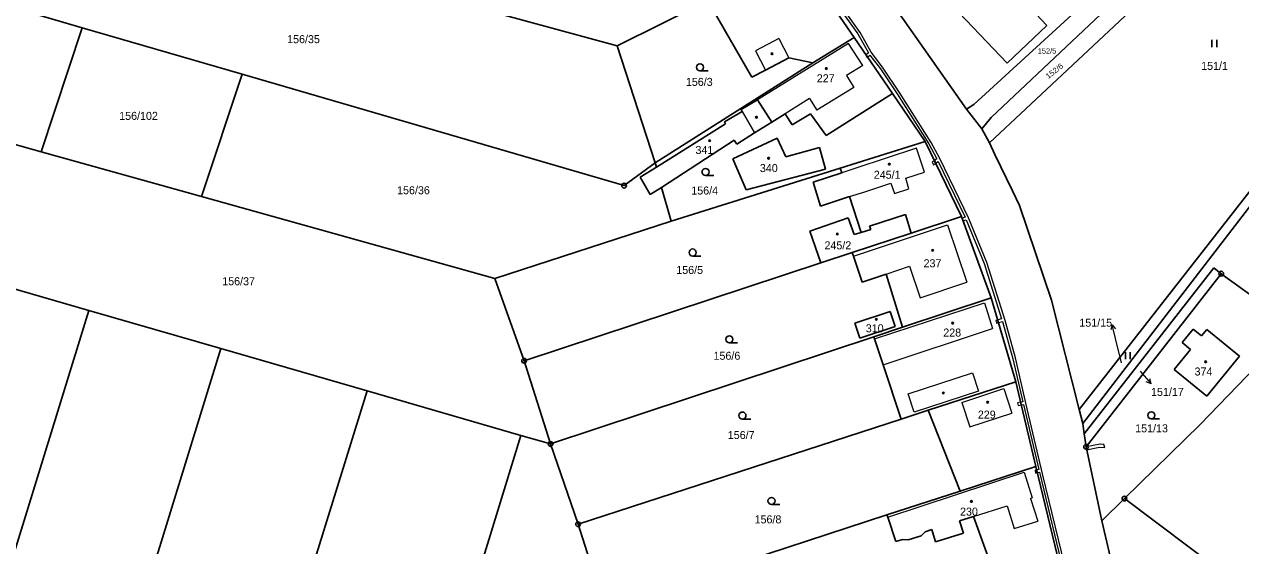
# Model space of a CAD drawing. Extents: x -694609 to -690140, y -1033292 to -1029794.
# Drawn here: x -693215.9 to -692957.6, y -1031527.4 to -1031416.8 of the extents above; entities that cross this region are included whole.
import ezdxf
from ezdxf.enums import TextEntityAlignment as Align

# ---------------------------------------------------------------- set-up
doc = ezdxf.new("R2010")
doc.units = 0
doc.header["$LTSCALE"] = 0.68
for name, color, linetype, lineweight in [('1', 7, 'Continuous', 25), ('13', 7, 'Continuous', 13), ('3', 7, 'Continuous', 25), ('4', 7, 'Continuous', 13), ('5', 7, 'Continuous', 25), ('7', 7, 'Continuous', 13), ('8', 7, 'Continuous', 25)]:
    doc.layers.add(name, color=color, linetype=linetype, lineweight=lineweight)
doc.layers.add('2', color=7, linetype='Continuous')

msp = doc.modelspace()

# ---------------------------------------------------------------- linework, layer by layer
at = {"layer": '1'}
for p, q in [((-693051.61, -1031402.21), (-693039.68, -1031419.57)), ((-693011.83, -1031403.18), (-692998.78, -1031416.98)), ((-693237.08, -1031407.73), (-693203.62, -1031417.48)), ((-693140.45, -1031407.6), (-693090.02, -1031421.29)), ((-693014.28, -1031433.8), (-692986.21, -1031408.04)), ((-693070.81, -1031411.75), (-693090.02, -1031421.29)), ((-693070.81, -1031411.75), (-693061.47, -1031427.99)), ((-693015.83, -1031434.75), (-693033.09, -1031410.25)), ((-693020.29, -1031411.17), (-693007.24, -1031424.98)), ((-692983.67, -1031411.06), (-693010.61, -1031436.53)), ((-692981.2, -1031414), (-693010.99, -1031441.88)), ((-693007.24, -1031424.98), (-692998.78, -1031416.98)), ((-693212.35, -1031443.81), (-693203.62, -1031417.48)), ((-693203.62, -1031417.48), (-693169.7, -1031427.36)), ((-693048.52, -1031424.96), (-693039.68, -1031419.57)), ((-693039.68, -1031419.57), (-693031.59, -1031431.43)), ((-693090.02, -1031421.29), (-693081.98, -1031446.14)), ((-693048.52, -1031424.96), (-693081.98, -1031446.14)), ((-693058.55, -1031426.46), (-693053.6, -1031423.87)), ((-693053.6, -1031423.87), (-693048.52, -1031424.96)), ((-693178.3, -1031453.32), (-693169.7, -1031427.36)), ((-693169.7, -1031427.36), (-693088.55, -1031451)), ((-693061.47, -1031427.99), (-693058.55, -1031426.46)), ((-693031.59, -1031431.43), (-693045.62, -1031440.32)), ((-693031.59, -1031431.43), (-693024.65, -1031441.66)), ((-693063.49, -1031435.23), (-693067.26, -1031437.47)), ((-693060.21, -1031432.75), (-693063.69, -1031434.87)), ((-693063.69, -1031434.87), (-693063.49, -1031435.23)), ((-693060.21, -1031432.75), (-693057.2, -1031437.53)), ((-693015.83, -1031434.75), (-693014.28, -1031433.8)), ((-693012.6, -1031438.91), (-693015.83, -1031434.75)), ((-692991.15, -1031501.5), (-692938.66, -1031433.21)), ((-693067.04, -1031437.88), (-693081.68, -1031447.05)), ((-693067.04, -1031437.88), (-693067.26, -1031437.47)), ((-693057.2, -1031437.53), (-693060.84, -1031439.82)), ((-693054.39, -1031435.77), (-693057.2, -1031437.53)), ((-693052.85, -1031438.09), (-693054.39, -1031435.77)), ((-693052.85, -1031438.09), (-693048.98, -1031435.74)), ((-693045.62, -1031440.32), (-693048.98, -1031435.74)), ((-693012.6, -1031438.91), (-693010.61, -1031436.53)), ((-693060.84, -1031439.82), (-693064.61, -1031442.21)), ((-693010.99, -1031441.88), (-693012.6, -1031438.91)), ((-693080.65, -1031451.39), (-693065.18, -1031441.34)), ((-693056.05, -1031440.94), (-693065.46, -1031445.3)), ((-693064.61, -1031442.21), (-693065.18, -1031441.34)), ((-693056.05, -1031440.94), (-693054.22, -1031444.86)), ((-693054.22, -1031444.86), (-693047.05, -1031442.92)), ((-693045.81, -1031447.51), (-693047.05, -1031442.92)), ((-693024.65, -1031441.66), (-693042.68, -1031447.28)), ((-693016.92, -1031457.57), (-693024.65, -1031441.66)), ((-693010.99, -1031441.88), (-693009.87, -1031444.42)), ((-693212.35, -1031443.81), (-693178.3, -1031453.32)), ((-693065.46, -1031445.3), (-693062.66, -1031451.92)), ((-693009.87, -1031444.42), (-693006.07, -1031452.07)), ((-693081.98, -1031446.14), (-693088.55, -1031451)), ((-693081.68, -1031447.05), (-693085.14, -1031449.22)), ((-693081.98, -1031446.14), (-693081.68, -1031447.05)), ((-693042.68, -1031447.28), (-693078.54, -1031458.51)), ((-693062.66, -1031451.92), (-693045.81, -1031447.51)), ((-693042.35, -1031448.28), (-693042.68, -1031447.28)), ((-692991.91, -1031498.52), (-692952.37, -1031447.9)), ((-693085.14, -1031449.22), (-693083.05, -1031452.89)), ((-693048.41, -1031450.23), (-693042.35, -1031448.28)), ((-693046.85, -1031455.33), (-693048.41, -1031450.23)), ((-693178.3, -1031453.32), (-693116, -1031470.7)), ((-693083.05, -1031452.89), (-693080.65, -1031451.39)), ((-693080.65, -1031451.39), (-693078.54, -1031458.51)), ((-693040.69, -1031453.33), (-693046.85, -1031455.33)), ((-693038.2, -1031460.91), (-693040.69, -1031453.33)), ((-693006.07, -1031452.07), (-693004.58, -1031455.21)), ((-693004.58, -1031455.21), (-692997.84, -1031475.31)), ((-693078.54, -1031458.51), (-693116, -1031470.7)), ((-693041, -1031457.81), (-693049.14, -1031460.66)), ((-693039.73, -1031461.39), (-693041, -1031457.81)), ((-693028.84, -1031457.1), (-693036.44, -1031459.59)), ((-693027.58, -1031461.08), (-693028.84, -1031457.1)), ((-693016.92, -1031457.57), (-693010.59, -1031474.83)), ((-693049.14, -1031460.66), (-693046.78, -1031467.4)), ((-693038.2, -1031460.91), (-693039.73, -1031461.39)), ((-693036.18, -1031460.27), (-693038.2, -1031460.91)), ((-693036.44, -1031459.59), (-693036.18, -1031460.27)), ((-693039.83, -1031466), (-693040.1, -1031465.2)), ((-693039.83, -1031466), (-693037.98, -1031471.49)), ((-692990.85, -1031503.65), (-692963.35, -1031468.45)), ((-692963.35, -1031468.45), (-692961.77, -1031469.68)), ((-693230.03, -1031469.43), (-693202.25, -1031477.47)), ((-693116, -1031470.7), (-693109.8, -1031488.16)), ((-693037.98, -1031471.49), (-693032.9, -1031469.77)), ((-693032.9, -1031469.77), (-693029.45, -1031481.07)), ((-692990.47, -1031506.41), (-692961.77, -1031469.68)), ((-692961.77, -1031469.68), (-692946.55, -1031480.67)), ((-693029.45, -1031481.07), (-693010.59, -1031474.83)), ((-693010.59, -1031474.83), (-693005.39, -1031492.61)), ((-692997.84, -1031475.31), (-692991.91, -1031498.52)), ((-693202.25, -1031477.47), (-693256.34, -1031653.33)), ((-693202.25, -1031477.47), (-693174.19, -1031485.58)), ((-693039.57, -1031480.22), (-693032.08, -1031477.69)), ((-693032.08, -1031477.69), (-693031.01, -1031480.86)), ((-693039.57, -1031480.22), (-693038.49, -1031483.39)), ((-693031.01, -1031480.86), (-693038.49, -1031483.39)), ((-693035.54, -1031483.09), (-693029.45, -1031481.07)), ((-692970.03, -1031484.28), (-692967.72, -1031481.45)), ((-692967.72, -1031481.45), (-692965.96, -1031482.89)), ((-692965.96, -1031482.89), (-692964.83, -1031481.55)), ((-692964.83, -1031481.55), (-692957.91, -1031487.16)), ((-693104.17, -1031505.83), (-693035.54, -1031483.09)), ((-693035.54, -1031483.09), (-693035.41, -1031483.49)), ((-693035.41, -1031483.49), (-693033.56, -1031489.01)), ((-692968.26, -1031485.74), (-692970.03, -1031484.28)), ((-693174.19, -1031485.58), (-693228.65, -1031661.92)), ((-693174.19, -1031485.58), (-693143.12, -1031494.56)), ((-692971.75, -1031490.04), (-692968.26, -1031485.74)), ((-693104.17, -1031505.83), (-693109.8, -1031488.16)), ((-693033.56, -1031489.01), (-693029.72, -1031500.53)), ((-692952.35, -1031487.36), (-692966.24, -1031501.7)), ((-692957.91, -1031487.16), (-692964.84, -1031495.7)), ((-692964.84, -1031495.7), (-692971.75, -1031490.04)), ((-693143.12, -1031494.56), (-693197.95, -1031671.45)), ((-693143.12, -1031494.56), (-693110.49, -1031504)), ((-693005.39, -1031492.61), (-693023.97, -1031498.66)), ((-693001.15, -1031510.6), (-693005.39, -1031492.61)), ((-693023.97, -1031498.66), (-693029.72, -1031500.53)), ((-693023.97, -1031498.66), (-693017.21, -1031515.83)), ((-692991.91, -1031498.52), (-692991.15, -1031501.5)), ((-693029.72, -1031500.53), (-693098.34, -1031522.85)), ((-692990.85, -1031503.65), (-692991.15, -1031501.5)), ((-692966.24, -1031501.7), (-692982.32, -1031517.41)), ((-693110.49, -1031504), (-693165.07, -1031681.66)), ((-693110.49, -1031504), (-693104.17, -1031505.83)), ((-692990.47, -1031506.41), (-692990.85, -1031503.65)), ((-693098.34, -1031522.85), (-693104.17, -1031505.83)), ((-692987.13, -1031522.11), (-692990.47, -1031506.41)), ((-693017.21, -1031515.83), (-693001.15, -1031510.6)), ((-692996.59, -1031529.38), (-693001.15, -1031510.6)), ((-693017.21, -1031515.83), (-693032.75, -1031520.89)), ((-692987.13, -1031522.11), (-692982.32, -1031517.41)), ((-692982.32, -1031517.41), (-692952.88, -1031539.48)), ((-693092.7, -1031540.43), (-693098.34, -1031522.85)), ((-693032.75, -1031520.89), (-693092.7, -1031540.43)), ((-693032.58, -1031521.36), (-693032.75, -1031520.89)), ((-693030.87, -1031526.56), (-693032.58, -1031521.36)), ((-693017.33, -1031522.16), (-693014.39, -1031521.24)), ((-693017.33, -1031522.16), (-693016.51, -1031524.78)), ((-693014.39, -1031521.24), (-693011.22, -1031529.87)), ((-692975.92, -1031569.87), (-692987.13, -1031522.11)), ((-693025.51, -1031525.29), (-693028.26, -1031526.14)), ((-693024.63, -1031524.44), (-693025.51, -1031525.29)), ((-693024.63, -1031524.44), (-693023.24, -1031524.01)), ((-693022.42, -1031526.63), (-693023.24, -1031524.01)), ((-693016.51, -1031524.78), (-693022.42, -1031526.63)), ((-693029.48, -1031526.11), (-693030.87, -1031526.56)), ((-693028.26, -1031526.14), (-693029.48, -1031526.11))]:
    msp.add_line(p, q, dxfattribs=at)
for points in [[(-693245.93, -1031434.44), (-693221.97, -1031441.13), (-693212.35, -1031443.81)], [(-693040.1, -1031465.2), (-693027.58, -1031461.08), (-693016.92, -1031457.57)], [(-693109.8, -1031488.16), (-693046.78, -1031467.4), (-693040.1, -1031465.2)]]:
    msp.add_lwpolyline(points, dxfattribs=at)
at = {"layer": '13'}
for points in [[(-692994.31, -1031534.27), (-692999.62, -1031512.42), (-693002.94, -1031498.35), (-693005.43, -1031487.56), (-693007.67, -1031479.62), (-693011.56, -1031467.3), (-693015.45, -1031457.84), (-693021.52, -1031445.22), (-693023.37, -1031441.84), (-693030.06, -1031431.22), (-693033.66, -1031425.87), (-693036.1, -1031422.7), (-693038.41, -1031418.49), (-693043.23, -1031411.8)], [(-693043.71, -1031412.16), (-693038.92, -1031418.81), (-693036.7, -1031422.84), (-693037.18, -1031423.23), (-693036.85, -1031423.72), (-693036.37, -1031423.33), (-693034.14, -1031426.23), (-693030.57, -1031431.53), (-693023.88, -1031442.15), (-693022.14, -1031445.33), (-693022.69, -1031445.7), (-693022.42, -1031446.24), (-693021.87, -1031445.86), (-693016.17, -1031457.71), (-693016.79, -1031457.93), (-693016.58, -1031458.49), (-693015.93, -1031458.26), (-693012.12, -1031467.5), (-693008.41, -1031479.26), (-693009.23, -1031479.48), (-693009.06, -1031480.06), (-693008.24, -1031479.84), (-693006, -1031487.74), (-693003.9, -1031496.86), (-693004.37, -1031496.94), (-693004.23, -1031497.53), (-693003.77, -1031497.45), (-693000.52, -1031511.22), (-693000.97, -1031511.33), (-693000.83, -1031511.91), (-693000.38, -1031511.8), (-692994.88, -1031534.47)]]:
    msp.add_lwpolyline(points, dxfattribs=at)
for points in [[(-693037.18, -1031423.23), (-693037.26, -1031423.29), (-693036.93, -1031423.79), (-693036.85, -1031423.72)], [(-693023.17, -1031446.03), (-693022.88, -1031446.56), (-693022.42, -1031446.24), (-693022.69, -1031445.7)], [(-693009.63, -1031479.59), (-693009.47, -1031480.17), (-693009.06, -1031480.06), (-693009.23, -1031479.48)], [(-693005.03, -1031497.06), (-693004.89, -1031497.65), (-693004.23, -1031497.53), (-693004.37, -1031496.94)], [(-692987.61, -1031506.5), (-692986.5, -1031506.6), (-692986.71, -1031505.93), (-692987.48, -1031505.86), (-692990.47, -1031506.41), (-692990.34, -1031507.04)], [(-693001.3, -1031511.41), (-693001.17, -1031511.99), (-693000.83, -1031511.91), (-693000.97, -1031511.33)]]:
    msp.add_lwpolyline(points, close=True, dxfattribs=at)
at = {"layer": '3'}
for p, q in [((-692963.731, -1031421.58), (-692963.731, -1031420.08)), ((-692962.73, -1031421.58), (-692962.73, -1031420.08)), ((-693072.443, -1031426.63), (-693070.693, -1031426.63)), ((-693071.263, -1031448.84), (-693069.513, -1031448.84)), ((-693074.003, -1031465.94), (-693072.253, -1031465.94)), ((-693066.203, -1031484.37), (-693064.453, -1031484.37)), ((-692982.071, -1031487.81), (-692982.071, -1031486.31)), ((-692981.07, -1031487.81), (-692981.07, -1031486.31)), ((-693063.433, -1031500.55), (-693061.683, -1031500.55)), ((-692976.613, -1031500.5), (-692974.863, -1031500.5)), ((-693057.263, -1031518.67), (-693055.513, -1031518.67))]:
    msp.add_line(p, q, dxfattribs=at)
for centre in [(-693072.4429, -1031425.8798), (-693071.2629, -1031448.0898), (-693074.0029, -1031465.1898), (-693066.2029, -1031483.6198), (-693063.4329, -1031499.7998), (-692976.6129, -1031499.7498), (-693057.2629, -1031517.9198)]:
    msp.add_circle(centre, 0.75, dxfattribs=at)
at = {"layer": '4'}
for p, q in [((-693055.73, -1031419.8), (-693060.68, -1031422.39)), ((-693055.73, -1031419.8), (-693053.6, -1031423.87)), ((-693060.68, -1031422.39), (-693058.55, -1031426.46)), ((-693040.88, -1031420.8), (-693060.21, -1031432.75)), ((-693037.9, -1031425.5), (-693040.88, -1031420.8)), ((-693037.9, -1031425.5), (-693041.33, -1031427.63)), ((-693041.33, -1031427.63), (-693039.76, -1031430.16)), ((-693049.17, -1031432.52), (-693054.39, -1031435.77)), ((-693049.17, -1031432.52), (-693047.65, -1031435.01)), ((-693039.76, -1031430.16), (-693047.65, -1031435.01)), ((-693063.49, -1031435.23), (-693060.84, -1031439.82)), ((-693026.48, -1031443.05), (-693039.33, -1031447.31)), ((-693024.76, -1031448.12), (-693026.48, -1031443.05)), ((-693039.33, -1031447.31), (-693042.35, -1031448.28)), ((-693028.77, -1031449.44), (-693024.76, -1031448.12)), ((-693037.69, -1031452.36), (-693031.94, -1031450.48)), ((-693031.94, -1031450.48), (-693031.17, -1031452.66)), ((-693028.1, -1031451.64), (-693028.77, -1031449.44)), ((-693040.69, -1031453.33), (-693037.69, -1031452.36)), ((-693031.17, -1031452.66), (-693028.1, -1031451.64)), ((-693032.9, -1031469.77), (-693027.94, -1031468.11)), ((-693027.94, -1031468.11), (-693025.67, -1031474.84)), ((-693025.67, -1031474.84), (-693015.77, -1031471.51)), ((-693035.41, -1031483.49), (-693012.05, -1031475.88)), ((-693012.05, -1031475.88), (-693010.36, -1031481.29)), ((-693033.56, -1031489.01), (-693010.36, -1031481.29)), ((-693028.26, -1031495.21), (-693014.57, -1031490.72)), ((-693014.57, -1031490.72), (-693013.3, -1031494.64)), ((-693013.3, -1031494.64), (-693026.99, -1031499.11)), ((-693026.99, -1031499.11), (-693028.26, -1031495.21)), ((-693016.88, -1031497.03), (-693015.17, -1031502.22)), ((-693015.17, -1031502.22), (-693006.2, -1031499.26)), ((-693032.58, -1031521.36), (-693003.62, -1031511.84)), ((-693003.62, -1031511.84), (-693001.91, -1031517.27)), ((-693002.23, -1031517.37), (-693001.91, -1031517.27)), ((-693002.23, -1031517.37), (-693000.71, -1031522.22)), ((-693014.39, -1031521.24), (-693007.21, -1031518.99)), ((-693007.21, -1031518.99), (-693005.71, -1031523.79)), ((-693005.71, -1031523.79), (-693000.71, -1031522.22))]:
    msp.add_line(p, q, dxfattribs=at)
for points in [[(-693039.83, -1031466), (-693019.88, -1031459.29), (-693015.77, -1031471.51)], [(-693016.88, -1031497.03), (-693007.91, -1031494.07), (-693006.2, -1031499.26)]]:
    msp.add_lwpolyline(points, dxfattribs=at)
at = {"layer": '5'}
for centre in [(-693057.1568, -1031423.0092), (-693045.6168, -1031426.1392), (-693060.4568, -1031436.4692), (-693070.3868, -1031441.4392), (-693057.8868, -1031445.1692), (-693032.2468, -1031446.4392), (-693043.2768, -1031461.2592), (-693023.0368, -1031464.7292), (-693035.0168, -1031479.3892), (-693018.7868, -1031480.1692), (-692965.0668, -1031488.3892), (-693020.7568, -1031495.0192), (-693011.3468, -1031496.9692), (-693014.8068, -1031518.0292)]:
    msp.add_circle(centre, 0.175, dxfattribs=at)
at = {"layer": '7'}
for p, q in [((-692984.936, -1031480.508), (-692985.18, -1031481.601)), ((-692976.661, -1031493.055), (-692976.94, -1031491.971))]:
    msp.add_line(p, q, dxfattribs=at)
for points in [[(-692982.91, -1031488.63), (-692984.21, -1031483.42), (-692984.936, -1031480.508), (-692984.208, -1031481.359)], [(-692978.98, -1031490.38), (-692978.63, -1031490.79), (-692976.661, -1031493.055), (-692977.696, -1031492.628)]]:
    msp.add_lwpolyline(points, dxfattribs=at)
at = {"layer": '8'}
for centre, radius in [((-693088.55, -1031450.9999), 0.5), ((-693088.55, -1031450.9999), 0.0303), ((-692961.77, -1031469.6799), 0.5), ((-692961.77, -1031469.6799), 0.0303), ((-693109.8, -1031488.1599), 0.5), ((-693109.8, -1031488.1599), 0.0303), ((-693104.17, -1031505.8299), 0.5), ((-693104.17, -1031505.8299), 0.0303), ((-692990.47, -1031506.4099), 0.5), ((-692990.47, -1031506.4099), 0.0303), ((-692982.32, -1031517.4099), 0.5), ((-692982.32, -1031517.4099), 0.0303), ((-693098.34, -1031522.8499), 0.5), ((-693098.34, -1031522.8499), 0.0303)]:
    msp.add_circle(centre, radius, dxfattribs=at)

# ---------------------------------------------------------------- texts
at = {"layer": '2'}
for s, height, p in [('156/35', 1.7, (-693156.64, -1031420.755)), ('152/5', 1.14, (-692998.759, -1031422.975)), ('151/1', 1.7, (-692963.18, -1031426.425)), ('227', 1.7, (-693045.749, -1031429.055)), ('156/3', 1.7, (-693072.6, -1031429.825)), ('341', 1.7, (-693071.509, -1031444.275)), ('340', 1.7, (-693057.839, -1031448.115)), ('245/1', 1.7, (-693032.7, -1031449.535)), ('156/36', 1.7, (-693133.29, -1031452.825)), ('156/4', 1.7, (-693071.45, -1031452.885)), ('245/2', 1.7, (-693043.17, -1031464.515)), ('156/5', 1.7, (-693074.64, -1031469.745)), ('237', 1.7, (-693023.079, -1031468.325)), ('156/37', 1.7, (-693170.42, -1031472.135)), ('310', 1.7, (-693035.349, -1031482.125)), ('228', 1.7, (-693018.889, -1031483.025)), ('156/6', 1.7, (-693066.73, -1031487.955)), ('374', 1.7, (-692965.529, -1031491.295)), ('229', 1.7, (-693011.549, -1031500.445)), ('151/13', 1.7, (-692976.56, -1031503.355)), ('156/7', 1.7, (-693063.7, -1031504.775)), ('230', 1.7, (-693015.329, -1031521.035)), ('156/8', 1.7, (-693058.01, -1031522.685))]:
    msp.add_text(s, height=height, dxfattribs=at).set_placement(p, align=Align.CENTER)
at = {"layer": '2', "width": 1.1}
msp.add_text('152/6', height=1.14, rotation=38, dxfattribs=at).set_placement((-692996.8359, -1031427.1047), align=Align.CENTER)
at = {"layer": '2'}
for s, p in [('156/102', (-693195.78, -1031437.035)), ('151/17', (-692976.67, -1031495.625))]:
    msp.add_text(s, height=1.7, dxfattribs=at).set_placement(p)
msp.add_text('151/15', height=1.7, dxfattribs=at).set_placement((-692984.939, -1031480.935), align=Align.RIGHT)

doc.saveas('drawing.dxf')
